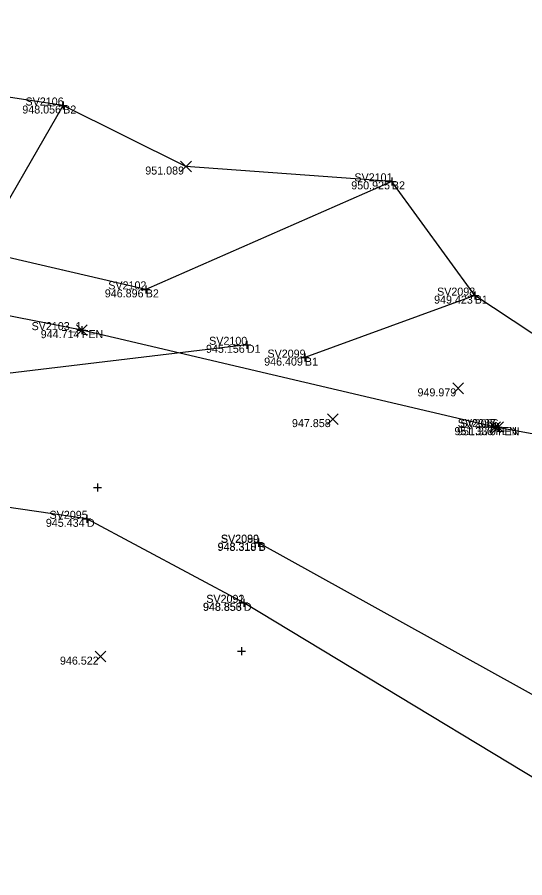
# Model space of a CAD drawing. Extents: x 2065431 to 2068157, y 709104 to 709719.
# Drawn here: x 2066416.8 to 2066480.2, y 709593.7 to 709701.2 of the extents above; entities that cross this region are included whole.
import ezdxf

# ---------------------------------------------------------------- set-up
doc = ezdxf.new("R2010")
doc.units = 0
for name, color, linetype in [('DT_X_Terrain_Boundary', 7, 'Continuous'), ('RD_X_Fence', 7, 'Continuous'), ('RS_Raster1', 7, 'Continuous'), ('RW_X_CL_100_Bearings', 7, 'Continuous'), ('RW_X_Fee_WL', 7, 'Continuous'), ('SV_X_Break_Lines', 7, 'Continuous'), ('SV_X_Mon_Cells_Found', 7, 'Continuous'), ('SV_X_Text_Elevation', 7, 'Continuous'), ('SV_X_Text_Name', 7, 'Continuous')]:
    doc.layers.add(name, color=color, linetype=linetype)

msp = doc.modelspace()

# ---------------------------------------------------------------- linework, layer by layer
at = {"layer": 'DT_X_Terrain_Boundary'}
msp.add_lwpolyline([(2066649.44, 709584.58), (2066543.44, 709596.37), (2066510.56, 709629.51), (2066507.17, 709644.46), (2066473.93, 709666.44), (2066463.59, 709680.71), (2066437.89, 709682.56), (2066422.56, 709690.18), (2066414.56, 709691.38), (2066359.14, 709688.04), (2066325.73, 709701.2), (2066327.01, 709677.48), (2066325.95, 709651.36), (2066268.91, 709598.56), (2066231.54, 709603.08), (2066151.93, 709594.95), (2066146.99, 709595.72), (2066142.05, 709596.5), (2066137.11, 709597.27), (2066132.17, 709598.05)], dxfattribs=at)
at = {"layer": 'RD_X_Fence'}
msp.add_lwpolyline([(2066507.17, 709644.46), (2066476.5, 709650.02), (2066424.89, 709662.13), (2066402.33, 709666.52), (2066368.48, 709673.58)], dxfattribs=at)
at = {"layer": 'RS_Raster1'}
for p, q in [((2066422.06, 709690.18), (2066423.06, 709690.18)), ((2066422.56, 709690.68), (2066422.56, 709689.68)), ((2066422.56, 709690.18), (2066422.56, 709690.18)), ((2066463.09, 709680.71), (2066464.09, 709680.71)), ((2066463.59, 709681.21), (2066463.59, 709680.21)), ((2066463.59, 709680.71), (2066463.59, 709680.71)), ((2066432.87, 709667.72), (2066432.87, 709666.72)), ((2066432.37, 709667.22), (2066433.37, 709667.22)), ((2066432.87, 709667.22), (2066432.87, 709667.22)), ((2066473.93, 709666.94), (2066473.93, 709665.94)), ((2066473.43, 709666.44), (2066474.43, 709666.44)), ((2066473.93, 709666.44), (2066473.93, 709666.44)), ((2066424.89, 709662.63), (2066424.89, 709661.63)), ((2066424.39, 709662.13), (2066425.39, 709662.13)), ((2066424.89, 709662.13), (2066424.89, 709662.13)), ((2066444.99, 709660.3), (2066445.99, 709660.3)), ((2066445.49, 709660.8), (2066445.49, 709659.8)), ((2066445.49, 709660.3), (2066445.49, 709660.3)), ((2066452.74, 709659.2), (2066452.74, 709658.2)), ((2066452.24, 709658.7), (2066453.24, 709658.7)), ((2066452.74, 709658.7), (2066452.74, 709658.7)), ((2066476.5, 709650.52), (2066476.5, 709649.52)), ((2066476.84, 709650.5), (2066476.84, 709649.5)), ((2066476, 709650.02), (2066477, 709650.02)), ((2066476.34, 709650), (2066477.34, 709650)), ((2066476.5, 709650.02), (2066476.5, 709650.02)), ((2066476.84, 709650), (2066476.84, 709650)), ((2066426.83, 709642.98), (2066426.83, 709641.98)), ((2066426.33, 709642.48), (2066427.33, 709642.48)), ((2066426.83, 709642.48), (2066426.83, 709642.48)), ((2066425.53, 709639.07), (2066425.53, 709638.07)), ((2066425.03, 709638.57), (2066426.03, 709638.57)), ((2066425.53, 709638.57), (2066425.53, 709638.57)), ((2066446.43, 709635.56), (2066447.43, 709635.56)), ((2066446.46, 709635.6), (2066447.46, 709635.6)), ((2066446.93, 709636.06), (2066446.93, 709635.06)), ((2066446.93, 709635.56), (2066446.93, 709635.56)), ((2066446.96, 709636.1), (2066446.96, 709635.1)), ((2066446.96, 709635.6), (2066446.96, 709635.6)), ((2066444.6, 709628.08), (2066445.6, 709628.08)), ((2066444.61, 709628.08), (2066445.61, 709628.08)), ((2066445.1, 709628.58), (2066445.1, 709627.58)), ((2066445.1, 709628.08), (2066445.1, 709628.08)), ((2066445.11, 709628.58), (2066445.11, 709627.58)), ((2066445.11, 709628.08), (2066445.11, 709628.08)), ((2066444.81, 709622.55), (2066444.81, 709621.55)), ((2066444.31, 709622.05), (2066445.31, 709622.05)), ((2066444.81, 709622.05), (2066444.81, 709622.05))]:
    msp.add_line(p, q, dxfattribs=at)
at = {"layer": 'RW_X_CL_100_Bearings'}
for p, q in [((2066437.22, 709681.9), (2066438.56, 709683.23)), ((2066437.22, 709683.23), (2066438.56, 709681.9)), ((2066424.22, 709661.46), (2066425.55, 709662.8)), ((2066424.22, 709662.8), (2066425.55, 709661.46)), ((2066471.21, 709654.19), (2066472.54, 709655.53)), ((2066471.21, 709655.53), (2066472.54, 709654.19)), ((2066455.55, 709650.35), (2066456.88, 709651.68)), ((2066455.55, 709651.68), (2066456.88, 709650.35)), ((2066475.83, 709649.35), (2066477.17, 709650.68)), ((2066475.83, 709650.68), (2066477.17, 709649.35)), ((2066476.17, 709649.34), (2066477.51, 709650.67)), ((2066476.17, 709650.67), (2066477.51, 709649.34)), ((2066426.57, 709620.69), (2066427.9, 709622.03)), ((2066426.57, 709622.03), (2066427.9, 709620.69))]:
    msp.add_line(p, q, dxfattribs=at)
at = {"layer": 'RW_X_Fee_WL'}
for points in [[(2066445.49, 709660.3), (2066411.76, 709656.24), (2066402.88, 709655.9), (2066396.53, 709650.4), (2066394.93, 709646.04), (2066394.4, 709644.52)], [(2066834.34, 709517.99), (2066792.15, 709523.14), (2066747.37, 709529.6), (2066701.7, 709535.47), (2066656.28, 709541.34), (2066614.98, 709547.01), (2066577.22, 709555.89), (2066538.15, 709580.88), (2066497.57, 709596.35), (2066445.11, 709628.08), (2066445.1, 709628.08), (2066425.53, 709638.57), (2066410.9, 709640.69), (2066399.97, 709646.12), (2066394.4, 709644.52), (2066392.47, 709644.49), (2066393.15, 709634.42)]]:
    msp.add_lwpolyline(points, dxfattribs=at)
at = {"layer": 'SV_X_Break_Lines'}
for points in [[(2066463.59, 709680.71), (2066432.87, 709667.22), (2066412.08, 709672.02), (2066422.56, 709690.18), (2066414.56, 709691.38), (2066405, 709675.72)], [(2066473.93, 709666.44), (2066452.74, 709658.7)], [(2066543.44, 709596.37), (2066501.38, 709605.41), (2066446.93, 709635.56), (2066446.96, 709635.6)]]:
    msp.add_lwpolyline(points, dxfattribs=at)

# ---------------------------------------------------------------- texts
at = {"layer": 'SV_X_Mon_Cells_Found'}
for s, p in [('SV2106', (2066417.86, 709690.18)), ('SV2101', (2066458.91, 709680.71)), ('SV2102', (2066428.19, 709667.22)), ('SV2098', (2066469.23, 709666.44)), ('SV2103_1', (2066418.62, 709662.13)), ('SV2100', (2066440.78, 709660.3)), ('SV2099', (2066448.06, 709658.7)), ('SV2087', (2066471.81, 709650.02)), ('SV2086', (2066472.14, 709650)), ('SV2095', (2066420.86, 709638.57)), ('SV2090', (2066442.25, 709635.6)), ('SV2089', (2066442.25, 709635.56)), ('SV2091', (2066440.43, 709628.08)), ('SV2092', (2066440.42, 709628.08))]:
    msp.add_text(s, height=1, dxfattribs=at).set_placement(p)
at = {"layer": 'SV_X_Text_Elevation'}
for s, p in [('B2', (2066422.56, 709689.18)), ('B2', (2066463.59, 709679.71)), ('B2', (2066432.87, 709666.22)), ('B1', (2066473.93, 709665.44)), ('FEN', (2066424.89, 709661.13)), ('D1', (2066445.49, 709659.3)), ('B1', (2066452.74, 709657.7)), ('FEN', (2066476.5, 709649.02)), ('FEN', (2066476.84, 709649)), ('D', (2066425.53, 709637.57)), ('B', (2066446.93, 709634.56)), ('B', (2066446.96, 709634.6)), ('D', (2066445.1, 709627.08)), ('D', (2066445.11, 709627.08))]:
    msp.add_text(s, height=1, dxfattribs=at).set_placement(p)
at = {"layer": 'SV_X_Text_Name'}
for s, p in [('948.056', (2066417.46, 709689.18)), ('951.089', (2066432.81, 709681.56)), ('950.925', (2066458.52, 709679.71)), ('946.896', (2066427.76, 709666.22)), ('949.423', (2066468.86, 709665.44)), ('944.714', (2066419.76, 709661.13)), ('944.714', (2066419.76, 709661.13)), ('945.156', (2066440.39, 709659.3)), ('946.409', (2066447.65, 709657.7)), ('949.979', (2066466.79, 709653.86)), ('947.858', (2066451.12, 709650.02)), ('951.338', (2066471.4, 709649.02)), ('951.338', (2066471.4, 709649.02)), ('951.370', (2066471.73, 709649)), ('951.370', (2066471.73, 709649)), ('945.434', (2066420.4, 709637.57)), ('948.318', (2066441.83, 709634.56)), ('948.310', (2066441.85, 709634.6)), ('948.856', (2066440, 709627.08)), ('948.853', (2066440.03, 709627.08)), ('946.522', (2066422.16, 709620.36))]:
    msp.add_text(s, height=1, dxfattribs=at).set_placement(p)

doc.saveas('drawing.dxf')
